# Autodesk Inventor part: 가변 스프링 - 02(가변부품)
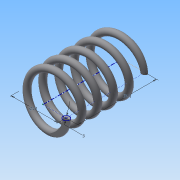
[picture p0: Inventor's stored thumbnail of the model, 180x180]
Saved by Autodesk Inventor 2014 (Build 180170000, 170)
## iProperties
Created: 2015-09
Part Number: 가변 스프링 - 02(가변부품)
Material: 강철, 탄소
Document SubType Name: Modeling
Designer: study
Density: 7.87 g/cm^3
Appearance: 반연마
Mass: 18.8486 g
Surface Area: 32.5049 cm^2
Volume: 2.39499 cm^3
Author: study
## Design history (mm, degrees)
sketch "스케치1"
  geometry: L1 (0, 32.577)-(11, 32.577); L2 (11, 32.577)-(11, 0); L3 (11, 0)-(0, 0); L4 (0, 0)-(0, 32.577); C1 r 1.5 at (11, 0); 1 further point
  constraints: 8 end point, 2 coincident, 2 parallel, 1 centre point, 1 horizontal, 1 perpendicular
  dimensions: "d0" = 3 diameter of C1; "d1" = 22 diameter of L2 L4; "d2" = 32.5769 distance of L1.end L2.end (derived)
feature "코일1" sketch "스케치1" pitch "d3" = 10; turns "d5" = 5; dims "d4" = 32.5769 (= d2), "d6" = 0, angle "d7" = 90 deg, angle "d8" = 90 deg, "d9" = 0, "d10" = 0
sketch "스케치2"
  geometry: L1 (-12.5, 0)-(-9.5, 0) reference; 1 further point
  constraints: 1 horizontal alignment
extrude "돌출1" cut sketch "스케치2" stored distance "d11" = 10; taper "d12" = 0 deg
node "작업 평면1"
sketch "스케치3"
  geometry: L1 (-9.5, 0)-(-12.5, 0) reference; 1 further point
  constraints: 1 horizontal alignment
extrude "돌출2" cut sketch "스케치3" stored distance "d14" = 10; taper "d15" = 0 deg
node "솔리드1"
node "절단 모서리 투영1"
node "절단 모서리 투영2"
other parameters: "d13" = 32.5769 (= d2)
